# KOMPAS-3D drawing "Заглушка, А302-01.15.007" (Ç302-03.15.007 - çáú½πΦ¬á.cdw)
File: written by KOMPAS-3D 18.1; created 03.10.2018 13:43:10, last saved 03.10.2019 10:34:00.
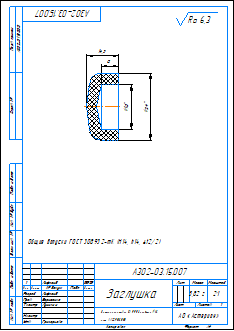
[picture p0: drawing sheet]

Sheet 1: A4, portrait

Document properties: Автор: Милов; Масса: 0.00581849; Параметр неуказанной шероховатости: Ra 6,3; Полное имя файла: ..\3Д ПВХ\А302-01.15.007 - Заглушка.m3d; Организация: Милов

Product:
- Part/product: Заглушка  | designation А302-01.15.007
    Масса: 0.00113785
    Раздел спецификации: Детали
    Форматы листов документа: A4
    source file: ..\3Д ПВХ\А302-01.15.007 - Заглушка.cdw
- Part/product: Заглушка  | designation А302-03.15.007
    Масса: 0.00581849
    Раздел спецификации: Детали
    Форматы листов документа: A4

Title block, sheet 1: Наименование: Заглушка; designation: А302-03.15.007; Масса: 5,82 г; scale: 2:1; Количество листов документа: 1; organisation: АО «Астерион»; Форматы листов документа: A4; stored path: \\192.168.87.28\Konstructor_doc\Мембранные насосы\Мембранный электропривод\А302-00.00.000 - ASTRA-302 (МЭ200)\3Д ПВХ\А302-01.15.007 - Заглушка.cdw; Разработал: Лифлянд; Проверил: Борисенко; Т. контр.: Лучихин; Утвердил: Григорьева

Views: Вид 1, Местный разрез 1, Спереди, Проекционный вид 2
Referenced files in D:\Мембранные насосы\Мембранный электропривод\А302-00.00.000 - ASTRA-302 (МЭ200)\3Д ПВХ\: А302-01.15.007 - Заглушка.m3d
Referenced files in Z:\Мембранные насосы\Мембранный электропривод\А302-00.00.000 - ASTRA-302 (МЭ200)\3Д ПВХ\: А302-01.15.007 - Заглушка.m3d
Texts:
  Деталь заготовка FV PPR Заглушка  16
  арт. AA229016000
  Ra 6,3
Dimensions and other numbers on the sheet: 8; 14,5; 16; 24; 2:1; 1; 5,82 г; 09.09.2019

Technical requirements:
  Общие допуски ГОСТ 30893.2-mK (H14, h14,  t2/2).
